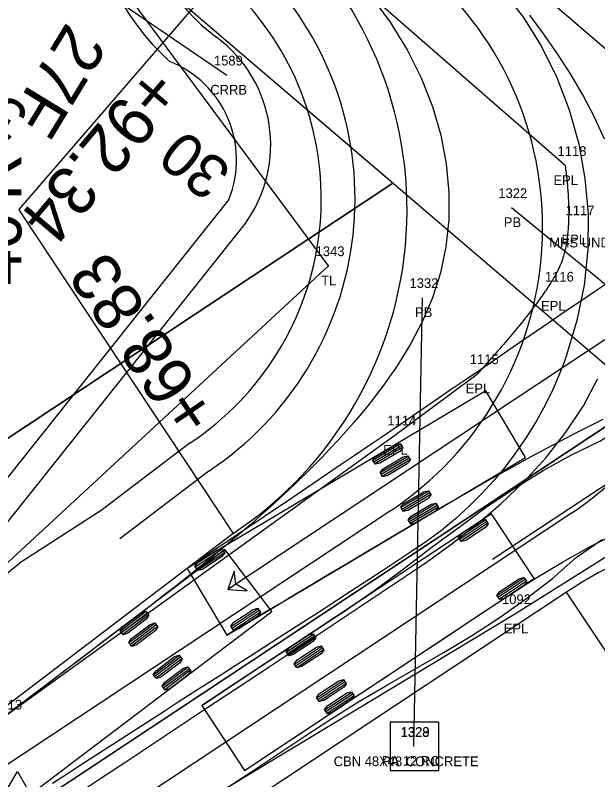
# Model space of a CAD drawing. Extents: x 1812113 to 1819860, y 1177290 to 1181185.
# Drawn here: x 1813743.6 to 1813803.6, y 1178588.3 to 1178667.1 of the extents above; entities that cross this region are included whole.
import ezdxf

# ---------------------------------------------------------------- set-up
doc = ezdxf.new("R2010")
doc.units = 0
for name, color, linetype in [('RD_EX_DR_Inlet', 7, 'Continuous'), ('RD_EX_DR_Inlet_txCode', 7, 'Continuous'), ('RD_EX_DR_Pipe', 7, 'Continuous'), ('RD_EX_DR_Pipe_txCode', 7, 'Continuous'), ('RD_EX_DV_Prop', 7, 'Continuous'), ('RD_EX_H2O', 7, 'Continuous'), ('RD_EX_H2O_txCode', 7, 'Continuous'), ('RD_EX_Road', 7, 'Continuous'), ('RD_EX_Road_txCode', 7, 'Continuous'), ('RD_EX_RW', 7, 'Continuous'), ('RD_EX_UT_txCode', 7, 'Continuous'), ('RD_EX_VEG', 7, 'Continuous'), ('RD_EX_VEG_txCode', 7, 'Continuous'), ('RD_HC_CL', 7, 'Continuous'), ('RD_HC_Data', 7, 'Continuous'), ('RD_PD_ALT1_TrvlWay', 7, 'Continuous'), ('RD_PD_ALT3_TnTmp', 7, 'Continuous'), ('RD_PD_CstnLmt', 7, 'Continuous'), ('RD_PD_DR_ErosCtrl', 7, 'Continuous'), ('RD_PD_Final_TnTmp', 7, 'Continuous'), ('RD_PD_GR', 7, 'Continuous'), ('RD_PD_PatLn1', 7, 'Continuous'), ('RD_Sketch10', 7, 'Continuous'), ('RD_Sketch6', 7, 'Continuous'), ('RD_Sketch7', 7, 'Continuous'), ('RD_Sketch8', 7, 'Continuous'), ('RD_SMD_Locator', 7, 'Continuous'), ('ROW_Obtain_T3', 7, 'Continuous')]:
    doc.layers.add(name, color=color, linetype=linetype)

msp = doc.modelspace()

# ---------------------------------------------------------------- linework, layer by layer
at = {"layer": 'RD_EX_DR_Inlet'}
msp.add_line((1813787.234, 1178589.245), (1813787.234, 1178594.245), dxfattribs=at)
msp.add_lwpolyline([(1813787.234, 1178589.245), (1813787.234, 1178594.245), (1813782.234, 1178594.245), (1813782.234, 1178589.245)], close=True, dxfattribs=at)
at = {"layer": 'RD_EX_DR_Pipe'}
for p, q in [((1813831.42, 1178617.18), (1813794.721, 1178647.236)), ((1813784.669, 1178591.737), (1813785.572, 1178637.964))]:
    msp.add_line(p, q, dxfattribs=at)
at = {"layer": 'RD_EX_DV_Prop'}
msp.add_line((1813747.534, 1178587.015), (1813808.574, 1178627.442), dxfattribs=at)
at = {"layer": 'RD_EX_H2O'}
msp.add_lwpolyline([(1813494.934, 1178677.139), (1813538.082, 1178685.025), (1813548.669, 1178684.396), (1813554.063, 1178674.831), (1813572.775, 1178667.802), (1813599.795, 1178663.176), (1813623.262, 1178662.124), (1813655.354, 1178662.604), (1813687.646, 1178668.532), (1813720.678, 1178667.781), (1813740.155, 1178669.888), (1813749.02, 1178672.079), (1813765.419, 1178660.888)], dxfattribs=at)
at = {"layer": 'RD_EX_Road'}
for p, q in [((1813800.257, 1178651.571), (1813775.579, 1178673.127)), ((1813782.718, 1178623.8), (1813791.219, 1178630.116)), ((1813742.113, 1178594.538), (1813782.718, 1178623.8)), ((1813815.993, 1178618.513), (1813795.139, 1178605.391)), ((1813795.139, 1178605.391), (1813756.931, 1178582.358))]:
    msp.add_line(p, q, dxfattribs=at)
msp.add_open_spline([(1813800.257, 1178651.571), (1813801.087, 1178645.461), (1813798.98, 1178638.625), (1813791.219, 1178630.116)], degree=2, dxfattribs=at)
at = {"layer": 'RD_EX_RW'}
for p, q in [((1813808.574, 1178627.442), (1813739.051, 1178686.932)), ((1813782.499, 1178649.754), (1813724.979, 1178611.658))]:
    msp.add_line(p, q, dxfattribs=at)
at = {"layer": 'RD_EX_VEG'}
msp.add_lwpolyline([(1813569.577, 1178500.764), (1813635.352, 1178535.148), (1813737.799, 1178606.062), (1813775.895, 1178641.246), (1813752.752, 1178672.453), (1813690.463, 1178652.624), (1813708.106, 1178634.089), (1813540.707, 1178531.719)], dxfattribs=at)
at = {"layer": 'RD_HC_CL'}
for p, q in [((1813850.516, 1178623.797), (1813755.38, 1178705.862)), ((1813829.909, 1178641.573), (1813743.828, 1178584.56))]:
    msp.add_line(p, q, dxfattribs=at)
at = {"layer": 'RD_HC_Data'}
for p, q in [((1813739.857, 1178582.268), (1813743.829, 1178589.147)), ((1813743.829, 1178589.147), (1813747.798, 1178582.268))]:
    msp.add_line(p, q, dxfattribs=at)
at = {"layer": 'RD_PD_ALT1_TrvlWay'}
for p, q in [((1813766.061, 1178613.679), (1813726.268, 1178583.405)), ((1813800.408, 1178607.64), (1813753.163, 1178576.35))]:
    msp.add_line(p, q, dxfattribs=at)
for centre, radius, start, end in [((1813743.974, 1178647.028), 40, 303.51678, 49.21843), ((1813825.256, 1178570.123), 45, 48.20181, 123.51678)]:
    msp.add_arc(centre, radius, start, end, dxfattribs=at)
at = {"layer": 'RD_PD_CstnLmt'}
msp.add_line((1813734.538, 1178604.47), (1813767.28, 1178645.585), dxfattribs=at)
for centre, radius, start, end in [((1813776.256, 1178680.863), 20, 139.21843, 233.42898), ((1813756.111, 1178653.709), 13.811, 323.96941, 53.42898)]:
    msp.add_arc(centre, radius, start, end, dxfattribs=at)
at = {"layer": 'RD_PD_DR_ErosCtrl'}
for p, q in [((1813765.623, 1178648.086), (1813758.886, 1178639.626)), ((1813758.886, 1178639.626), (1813732.882, 1178606.972)), ((1813758.886, 1178639.626), (1813758.886, 1178639.626))]:
    msp.add_line(p, q, dxfattribs=at)
for centre, radius, start, end in [((1813776.256, 1178680.863), 25, 139.21843, 227.94049), ((1813755.457, 1178652.136), 10.943, 338.27776, 68.2711)]:
    msp.add_arc(centre, radius, start, end, dxfattribs=at)
at = {"layer": 'RD_PD_Final_TnTmp'}
for p, q in [((1813743.974, 1178647.028), (1813770.101, 1178677.316)), ((1813743.974, 1178647.028), (1813766.061, 1178613.679)), ((1813825.286, 1178570.078), (1813800.408, 1178607.64))]:
    msp.add_line(p, q, dxfattribs=at)
at = {"layer": 'RD_PD_GR'}
msp.add_line((1813763.541, 1178620.1), (1813754.37, 1178613.122), dxfattribs=at)
msp.add_arc((1813744.954, 1178648.164), 33.661, 303.51678, 43.60848, dxfattribs=at)
at = {"layer": 'RD_PD_PatLn1'}
for p, q in [((1813761.619, 1178623.002), (1813752.447, 1178616.025)), ((1813752.447, 1178616.025), (1813744.04, 1178610.609)), ((1813696.765, 1178572.422), (1813744.04, 1178610.609))]:
    msp.add_line(p, q, dxfattribs=at)
msp.add_arc((1813744.954, 1178648.164), 30.18, 303.51678, 42.95891, dxfattribs=at)
at = {"layer": 'RD_Sketch10'}
for p, q in [((1813807.615, 1178620.81), (1813792.784, 1178610.987)), ((1813792.66, 1178615.703), (1813762.812, 1178595.935)), ((1813797.077, 1178609.033), (1813792.66, 1178615.703)), ((1813792.66, 1178615.703), (1813792.66, 1178615.703)), ((1813792.08, 1178615.069), (1813789.301, 1178613.228)), ((1813792.195, 1178614.895), (1813789.416, 1178613.054)), ((1813792.31, 1178614.721), (1813789.531, 1178612.881)), ((1813767.23, 1178589.265), (1813797.077, 1178609.033)), ((1813796.037, 1178609.094), (1813793.258, 1178607.253)), ((1813796.152, 1178608.92), (1813793.373, 1178607.079)), ((1813796.267, 1178608.746), (1813793.488, 1178606.906)), ((1813771.543, 1178601.467), (1813774.322, 1178603.307)), ((1813771.658, 1178601.293), (1813774.437, 1178603.134)), ((1813771.773, 1178601.119), (1813774.552, 1178602.96)), ((1813772.371, 1178600.216), (1813775.15, 1178602.057)), ((1813772.486, 1178600.042), (1813775.265, 1178601.883)), ((1813772.601, 1178599.869), (1813775.38, 1178601.709)), ((1813774.672, 1178596.742), (1813777.451, 1178598.583)), ((1813774.787, 1178596.569), (1813777.566, 1178598.409)), ((1813774.902, 1178596.395), (1813777.681, 1178598.235)), ((1813775.5, 1178595.492), (1813778.279, 1178597.332)), ((1813775.615, 1178595.318), (1813778.394, 1178597.159)), ((1813775.73, 1178595.144), (1813778.509, 1178596.985)), ((1813762.812, 1178595.935), (1813767.23, 1178589.265))]:
    msp.add_line(p, q, dxfattribs=at)
for points in [[(1813762.812, 1178595.935), (1813765.797, 1178597.911), (1813768.782, 1178599.888), (1813771.767, 1178601.865), (1813774.751, 1178603.842), (1813777.736, 1178605.819), (1813780.681, 1178607.857), (1813783.559, 1178610.001), (1813786.42, 1178612.195), (1813789.329, 1178614.339), (1813792.27, 1178616.474), (1813792.27, 1178616.474), (1813795.1, 1178618.376), (1813797.989, 1178620.158), (1813800.912, 1178621.791), (1813803.844, 1178623.168), (1813806.651, 1178624.969), (1813809.502, 1178626.753), (1813812.56, 1178628.27), (1813815.803, 1178629.493), (1813819.194, 1178630.407), (1813822.695, 1178631), (1813825.552, 1178631.236)], [(1813767.23, 1178589.265), (1813770.215, 1178591.242), (1813773.199, 1178593.218), (1813776.184, 1178595.195), (1813779.169, 1178597.172), (1813782.154, 1178599.149), (1813785.138, 1178601.126), (1813788.123, 1178603.102), (1813791.108, 1178605.079), (1813794.095, 1178607.053), (1813797.105, 1178608.991), (1813797.105, 1178608.991), (1813797.105, 1178608.991), (1813799.972, 1178610.734), (1813802.903, 1178612.369), (1813805.909, 1178613.859), (1813808.997, 1178615.169), (1813812.168, 1178616.263), (1813815.39, 1178617.103), (1813818.6, 1178617.659), (1813821.767, 1178617.92), (1813824.863, 1178617.889), (1813827.861, 1178617.574), (1813830.176, 1178617.128)]]:
    msp.add_lwpolyline(points, dxfattribs=at)
for points in [[(1813792.052, 1178615.112), (1813792.339, 1178614.678), (1813792.036, 1178614.29), (1813790.035, 1178612.965), (1813789.56, 1178612.838), (1813789.272, 1178613.271), (1813789.575, 1178613.66), (1813791.576, 1178614.985)], [(1813796.009, 1178609.137), (1813796.296, 1178608.703), (1813795.993, 1178608.315), (1813793.992, 1178606.99), (1813793.517, 1178606.863), (1813793.23, 1178607.296), (1813793.532, 1178607.685), (1813795.533, 1178609.01)], [(1813771.801, 1178601.076), (1813771.514, 1178601.51), (1813771.817, 1178601.898), (1813773.818, 1178603.223), (1813774.293, 1178603.35), (1813774.58, 1178602.917), (1813774.278, 1178602.529), (1813772.277, 1178601.203)], [(1813772.63, 1178599.826), (1813772.342, 1178600.259), (1813772.645, 1178600.647), (1813774.646, 1178601.973), (1813775.121, 1178602.1), (1813775.409, 1178601.666), (1813775.106, 1178601.278), (1813773.105, 1178599.953)], [(1813774.93, 1178596.352), (1813774.643, 1178596.785), (1813774.946, 1178597.174), (1813776.947, 1178598.499), (1813777.422, 1178598.626), (1813777.709, 1178598.192), (1813777.407, 1178597.804), (1813775.406, 1178596.479)], [(1813775.759, 1178595.101), (1813775.471, 1178595.535), (1813775.774, 1178595.923), (1813777.775, 1178597.248), (1813778.25, 1178597.375), (1813778.538, 1178596.942), (1813778.235, 1178596.554), (1813776.234, 1178595.228)]]:
    msp.add_lwpolyline(points, close=True, dxfattribs=at)
at = {"layer": 'RD_Sketch6'}
for p, q in [((1813811.555, 1178638.412), (1813765.504, 1178607.912)), ((1813792.085, 1178628.365), (1813761.311, 1178610.073)), ((1813796.173, 1178621.488), (1813792.085, 1178628.365)), ((1813783.309, 1178622.906), (1813780.444, 1178621.203)), ((1813783.416, 1178622.727), (1813780.55, 1178621.024)), ((1813783.522, 1178622.548), (1813780.657, 1178620.845)), ((1813765.398, 1178603.196), (1813796.173, 1178621.488)), ((1813784.075, 1178621.616), (1813781.21, 1178619.913)), ((1813784.182, 1178621.437), (1813781.316, 1178619.734)), ((1813784.288, 1178621.258), (1813781.423, 1178619.555)), ((1813786.204, 1178618.035), (1813783.339, 1178616.332)), ((1813786.311, 1178617.856), (1813783.445, 1178616.153)), ((1813786.417, 1178617.677), (1813783.552, 1178615.973)), ((1813786.971, 1178616.745), (1813784.105, 1178615.042)), ((1813787.077, 1178616.566), (1813784.212, 1178614.863)), ((1813787.184, 1178616.387), (1813784.318, 1178614.684)), ((1813762.151, 1178610.236), (1813764.931, 1178612.075)), ((1813762.266, 1178610.062), (1813765.046, 1178611.902)), ((1813762.381, 1178609.888), (1813765.161, 1178611.728)), ((1813761.311, 1178610.073), (1813765.398, 1178603.196)), ((1813765.848, 1178604.096), (1813768.626, 1178605.937)), ((1813765.963, 1178603.922), (1813768.741, 1178605.764)), ((1813766.078, 1178603.748), (1813768.856, 1178605.59)), ((1813765.398, 1178603.196), (1813765.398, 1178603.196))]:
    msp.add_line(p, q, dxfattribs=at)
for points in [[(1813804.828, 1178639.606), (1813803.297, 1178638.576), (1813801.778, 1178637.55), (1813800.272, 1178636.527), (1813798.775, 1178635.507), (1813797.289, 1178634.492), (1813795.811, 1178633.481), (1813794.341, 1178632.474), (1813792.878, 1178631.472), (1813791.422, 1178630.474), (1813789.971, 1178629.48), (1813788.525, 1178628.49), (1813787.085, 1178627.505), (1813785.648, 1178626.523), (1813784.215, 1178625.545), (1813782.786, 1178624.571), (1813781.36, 1178623.599), (1813779.936, 1178622.631), (1813778.515, 1178621.666), (1813777.097, 1178620.704), (1813775.68, 1178619.745), (1813774.265, 1178618.788), (1813772.852, 1178617.833), (1813771.441, 1178616.88), (1813770.03, 1178615.93), (1813768.621, 1178614.981), (1813767.214, 1178614.034), (1813765.807, 1178613.089), (1813764.401, 1178612.145), (1813762.996, 1178611.202), (1813761.592, 1178610.261), (1813761.311, 1178610.073)], [(1813804.15, 1178625.41), (1813802.89, 1178624.787), (1813801.609, 1178624.141), (1813800.311, 1178623.473), (1813798.998, 1178622.785), (1813797.673, 1178622.078), (1813796.336, 1178621.354), (1813794.99, 1178620.615), (1813793.637, 1178619.86), (1813792.276, 1178619.093), (1813790.91, 1178618.312), (1813789.539, 1178617.521), (1813788.164, 1178616.719), (1813786.785, 1178615.907), (1813785.404, 1178615.087), (1813784.017, 1178614.263), (1813782.625, 1178613.435), (1813781.229, 1178612.606), (1813779.829, 1178611.774), (1813778.426, 1178610.939), (1813777.019, 1178610.103), (1813775.61, 1178609.266), (1813774.198, 1178608.426), (1813772.783, 1178607.586), (1813771.367, 1178606.744), (1813769.948, 1178605.901), (1813768.528, 1178605.057), (1813767.106, 1178604.212), (1813765.683, 1178603.366), (1813765.398, 1178603.196)]]:
    msp.add_lwpolyline(points, dxfattribs=at)
for points in [[(1813783.283, 1178622.95), (1813783.548, 1178622.503), (1813783.227, 1178622.13), (1813781.164, 1178620.904), (1813780.683, 1178620.8), (1813780.417, 1178621.247), (1813780.738, 1178621.62), (1813782.801, 1178622.847)], [(1813784.049, 1178621.661), (1813784.315, 1178621.214), (1813783.994, 1178620.841), (1813781.931, 1178619.615), (1813781.449, 1178619.511), (1813781.184, 1178619.958), (1813781.505, 1178620.331), (1813783.568, 1178621.557)], [(1813786.178, 1178618.079), (1813786.444, 1178617.632), (1813786.123, 1178617.259), (1813784.059, 1178616.033), (1813783.578, 1178615.929), (1813783.313, 1178616.376), (1813783.634, 1178616.749), (1813785.697, 1178617.975)], [(1813786.944, 1178616.79), (1813787.21, 1178616.343), (1813786.889, 1178615.97), (1813784.826, 1178614.743), (1813784.345, 1178614.64), (1813784.079, 1178615.087), (1813784.4, 1178615.46), (1813786.463, 1178616.686)], [(1813762.409, 1178609.845), (1813762.122, 1178610.279), (1813762.425, 1178610.667), (1813764.427, 1178611.991), (1813764.902, 1178612.118), (1813765.189, 1178611.685), (1813764.886, 1178611.297), (1813762.885, 1178609.972)], [(1813765.504, 1178607.912), (1813767.499, 1178607.773), (1813766.337, 1178608.464), (1813766.154, 1178609.803)], [(1813766.106, 1178603.705), (1813765.819, 1178604.139), (1813766.121, 1178604.527), (1813768.122, 1178605.853), (1813768.597, 1178605.98), (1813768.885, 1178605.547), (1813768.582, 1178605.158), (1813766.582, 1178603.832)]]:
    msp.add_lwpolyline(points, close=True, dxfattribs=at)
at = {"layer": 'RD_Sketch7'}
msp.add_line((1813800.917, 1178615.774), (1813746.865, 1178579.975), dxfattribs=at)
for points in [[(1813804.319, 1178654.292), (1813803.247, 1178656.623), (1813802.065, 1178658.861), (1813800.796, 1178661.018), (1813799.459, 1178663.101), (1813798.065, 1178665.118), (1813796.625, 1178667.078)], [(1813749.527, 1178586.535), (1813752.313, 1178588.381), (1813755.099, 1178590.226), (1813757.885, 1178592.071), (1813760.671, 1178593.917), (1813763.458, 1178595.762), (1813766.244, 1178597.607), (1813769.03, 1178599.453), (1813771.816, 1178601.298), (1813774.602, 1178603.143), (1813777.388, 1178604.989), (1813780.175, 1178606.834), (1813782.959, 1178608.682), (1813785.722, 1178610.561), (1813788.44, 1178612.506), (1813791.084, 1178614.548), (1813793.629, 1178616.713), (1813796.042, 1178619.022), (1813798.295, 1178621.487), (1813800.346, 1178624.109), (1813802.137, 1178626.839), (1813803.643, 1178629.647)], [(1813765.089, 1178587.247), (1813767.875, 1178589.092), (1813770.661, 1178590.938), (1813773.447, 1178592.783), (1813776.238, 1178594.622), (1813779.077, 1178596.389), (1813781.97, 1178598.081), (1813784.889, 1178599.753), (1813787.808, 1178601.45), (1813790.706, 1178603.209), (1813793.554, 1178605.056), (1813796.32, 1178607.002), (1813798.966, 1178609.038), (1813801.386, 1178611.185), (1813804.095, 1178613.081)]]:
    msp.add_lwpolyline(points, dxfattribs=at)
msp.add_arc((1813781.591, 1178644.954), 35, 303.51678, 49.21843, dxfattribs=at)
at = {"layer": 'RD_Sketch8'}
for p, q in [((1813782.266, 1178616.015), (1813741.076, 1178588.735)), ((1813765.212, 1178612.024), (1813736.669, 1178590.415)), ((1813770.041, 1178605.645), (1813765.212, 1178612.024)), ((1813741.497, 1178584.037), (1813770.041, 1178605.645)), ((1813757.099, 1178605.621), (1813754.441, 1178603.609)), ((1813757.225, 1178605.454), (1813754.567, 1178603.443)), ((1813757.351, 1178605.288), (1813754.693, 1178603.276)), ((1813758.005, 1178604.425), (1813755.347, 1178602.413)), ((1813758.13, 1178604.259), (1813755.473, 1178602.247)), ((1813758.256, 1178604.092), (1813755.598, 1178602.08)), ((1813760.519, 1178601.103), (1813757.862, 1178599.091)), ((1813760.645, 1178600.936), (1813757.988, 1178598.925)), ((1813760.771, 1178600.77), (1813758.113, 1178598.758)), ((1813761.425, 1178599.907), (1813758.767, 1178597.895)), ((1813761.551, 1178599.74), (1813758.893, 1178597.729)), ((1813761.676, 1178599.574), (1813759.019, 1178597.562))]:
    msp.add_line(p, q, dxfattribs=at)
for points in [[(1813793.847, 1178669.591), (1813795.958, 1178666.835), (1813797.815, 1178663.85), (1813799.397, 1178660.665), (1813800.683, 1178657.315), (1813801.656, 1178653.83), (1813802.302, 1178650.246), (1813802.613, 1178646.597), (1813802.58, 1178642.916), (1813802.202, 1178639.24), (1813801.478, 1178635.603), (1813800.413, 1178632.039), (1813800.16, 1178631.338)], [(1813780.283, 1178669.034), (1813782.237, 1178666.341), (1813783.97, 1178663.514), (1813785.428, 1178660.611), (1813786.591, 1178657.665), (1813787.454, 1178654.702), (1813788.016, 1178651.75), (1813788.283, 1178648.833), (1813788.264, 1178645.973), (1813787.969, 1178643.194), (1813787.412, 1178640.515), (1813786.608, 1178637.955), (1813785.576, 1178635.529), (1813784.367, 1178633.234), (1813783.026, 1178631.056), (1813782.745, 1178630.633)], [(1813800.16, 1178631.338), (1813799.755, 1178630.295), (1813799.015, 1178628.582), (1813798.193, 1178626.904), (1813797.293, 1178625.265), (1813796.316, 1178623.668), (1813795.263, 1178622.119), (1813794.137, 1178620.619), (1813792.941, 1178619.173), (1813791.677, 1178617.784), (1813790.348, 1178616.456), (1813788.957, 1178615.192), (1813787.506, 1178613.994), (1813786, 1178612.865), (1813784.446, 1178611.805), (1813782.891, 1178610.772), (1813781.341, 1178609.752), (1813779.799, 1178608.744), (1813778.264, 1178607.747), (1813776.737, 1178606.76), (1813775.217, 1178605.781), (1813773.705, 1178604.809), (1813772.2, 1178603.844), (1813770.702, 1178602.885), (1813769.21, 1178601.931), (1813767.726, 1178600.981), (1813766.248, 1178600.035), (1813764.775, 1178599.092), (1813763.308, 1178598.152), (1813761.847, 1178597.215), (1813760.39, 1178596.279), (1813758.938, 1178595.346), (1813757.491, 1178594.414), (1813756.047, 1178593.483), (1813754.607, 1178592.554), (1813753.171, 1178591.625), (1813751.738, 1178590.698), (1813750.308, 1178589.771), (1813748.88, 1178588.845), (1813747.456, 1178587.919)], [(1813782.745, 1178630.633), (1813782.317, 1178630.007), (1813781.585, 1178628.983), (1813780.835, 1178627.982), (1813780.067, 1178627.002), (1813779.284, 1178626.043), (1813778.488, 1178625.103), (1813777.68, 1178624.181), (1813776.86, 1178623.276), (1813776.031, 1178622.386), (1813775.193, 1178621.512), (1813774.346, 1178620.651), (1813773.493, 1178619.804), (1813772.632, 1178618.968), (1813771.763, 1178618.142), (1813770.857, 1178617.299), (1813769.909, 1178616.432), (1813768.922, 1178615.548), (1813767.899, 1178614.648), (1813766.844, 1178613.736), (1813765.759, 1178612.814), (1813764.647, 1178611.884), (1813763.51, 1178610.947), (1813762.351, 1178610.006), (1813761.171, 1178609.062), (1813759.973, 1178608.114), (1813758.758, 1178607.165), (1813757.527, 1178606.215), (1813756.283, 1178605.264), (1813755.026, 1178604.313), (1813753.762, 1178603.356), (1813752.492, 1178602.394), (1813751.216, 1178601.428), (1813749.935, 1178600.458), (1813748.649, 1178599.485), (1813747.359, 1178598.508), (1813746.065, 1178597.529), (1813744.768, 1178596.547), (1813743.468, 1178595.563)]]:
    msp.add_lwpolyline(points, dxfattribs=at)
for points in [[(1813757.068, 1178605.662), (1813757.382, 1178605.247), (1813757.104, 1178604.841), (1813755.191, 1178603.392), (1813754.724, 1178603.235), (1813754.41, 1178603.65), (1813754.688, 1178604.056), (1813756.601, 1178605.505)], [(1813757.973, 1178604.466), (1813758.287, 1178604.051), (1813758.01, 1178603.645), (1813756.096, 1178602.196), (1813755.63, 1178602.039), (1813755.316, 1178602.454), (1813755.593, 1178602.86), (1813757.507, 1178604.309)], [(1813760.488, 1178601.144), (1813760.802, 1178600.729), (1813760.525, 1178600.323), (1813758.611, 1178598.874), (1813758.144, 1178598.717), (1813757.831, 1178599.132), (1813758.108, 1178599.538), (1813760.022, 1178600.987)], [(1813761.394, 1178599.948), (1813761.707, 1178599.533), (1813761.43, 1178599.127), (1813759.516, 1178597.678), (1813759.05, 1178597.521), (1813758.736, 1178597.936), (1813759.013, 1178598.342), (1813760.927, 1178599.791)]]:
    msp.add_lwpolyline(points, close=True, dxfattribs=at)
msp.add_arc((1813762.939, 1178645.195), 35, 303.51678, 49.21843, dxfattribs=at)
at = {"layer": 'RD_SMD_Locator'}
for centre in [(1813765.419, 1178660.888), (1813800.257, 1178651.571), (1813794.721, 1178647.236), (1813801.087, 1178645.461), (1813775.895, 1178641.246), (1813798.98, 1178638.625), (1813785.572, 1178637.964), (1813791.219, 1178630.116), (1813782.718, 1178623.8), (1813795.139, 1178605.391), (1813784.669, 1178591.737)]:
    msp.add_circle(centre, 0.001, dxfattribs=at)
at = {"layer": 'ROW_Obtain_T3'}
for p, q in [((1813782.499, 1178649.754), (1813739.051, 1178686.932)), ((1813739, 1178620.944), (1813782.499, 1178649.754))]:
    msp.add_line(p, q, dxfattribs=at)

# ---------------------------------------------------------------- texts
at = {"layer": 'RD_EX_DR_Inlet_txCode'}
for s, p in [('1328', (1813783.297, 1178592.7)), ('CBN 48X48 CONCRETE', (1813776.411, 1178589.7))]:
    msp.add_text(s, height=1, dxfattribs=at).set_placement(p)
at = {"layer": 'RD_EX_DR_Pipe_txCode'}
for s, p in [('1322', (1813793.375, 1178648.236)), ('PB', (1813793.941, 1178645.236)), ('1332', (1813784.225, 1178638.964)), ('PB', (1813784.792, 1178635.964)), ('1329', (1813783.323, 1178592.737)), ('PA 12 RC', (1813781.378, 1178589.737))]:
    msp.add_text(s, height=1, dxfattribs=at).set_placement(p)
at = {"layer": 'RD_EX_H2O_txCode'}
for s, p in [('1589', (1813764.073, 1178661.888)), ('CRRB', (1813763.695, 1178658.888))]:
    msp.add_text(s, height=1, dxfattribs=at).set_placement(p)
at = {"layer": 'RD_EX_Road_txCode'}
for s, p in [('1118', (1813799.477, 1178652.571)), ('EPL', (1813799.052, 1178649.571)), ('1117', (1813800.307, 1178646.461)), ('EPL', (1813799.882, 1178643.461)), ('1116', (1813798.176, 1178639.625)), ('EPL', (1813797.775, 1178636.625)), ('1115', (1813790.439, 1178631.116)), ('EPL', (1813790.014, 1178628.116)), ('1114', (1813781.938, 1178624.8)), ('EPL', (1813781.513, 1178621.8)), ('1092', (1813793.753, 1178606.391)), ('EPL', (1813793.934, 1178603.391)), ('1113', (1813741.334, 1178595.538))]:
    msp.add_text(s, height=1, dxfattribs=at).set_placement(p)
at = {"layer": 'RD_EX_UT_txCode'}
msp.add_text('MHS UNDER PAVEMENT', height=1, dxfattribs=at).set_placement((1813798.622, 1178643.143))
at = {"layer": 'RD_EX_VEG_txCode'}
for s, p in [('1343', (1813774.549, 1178642.246)), ('TL', (1813775.123, 1178639.246))]:
    msp.add_text(s, height=1, dxfattribs=at).set_placement(p)
at = {"layer": 'RD_PD_ALT3_TnTmp'}
for s, rotation, p in [('+92.34', 229.82098, (1813757.262, 1178662.084)), ("40'R", 90.14619, (1813744.255, 1178639.241)), ('+68.83', 124.2931, (1813764.658, 1178625.966))]:
    msp.add_text(s, height=5, rotation=rotation, dxfattribs=at).set_placement(p)
at = {"layer": 'RD_PD_CstnLmt'}
msp.add_text('27F', height=5, rotation=238.61395, dxfattribs=at).set_placement((1813748.952, 1178666.472))
at = {"layer": 'RD_PD_DR_ErosCtrl'}
for rotation, p in [(148.54433, (1813745.267, 1178657.299)), (140.83178, (1813766.102, 1178651.208))]:
    msp.add_text('30', height=4.5, rotation=rotation, dxfattribs=at).set_placement(p)

doc.saveas('drawing.dxf')
